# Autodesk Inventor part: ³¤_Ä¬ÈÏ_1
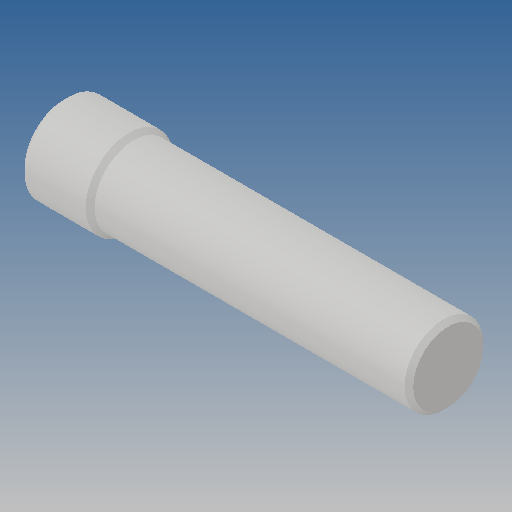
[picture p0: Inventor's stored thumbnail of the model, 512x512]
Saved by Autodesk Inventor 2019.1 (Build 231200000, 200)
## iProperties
Created: 2012-10
Part Number: ³¤_Ä¬ÈÏ_1
Material: Ogólny
Document SubType Name: Modeling
Designer: CADENGINEERING4
Density: 1 g/cm^3
Appearance: Domyślna
Author: CADENGINEERING4
Revision Number: ÈÎºÎ
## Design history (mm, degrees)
feature "NONE"
node "Bryła1"
